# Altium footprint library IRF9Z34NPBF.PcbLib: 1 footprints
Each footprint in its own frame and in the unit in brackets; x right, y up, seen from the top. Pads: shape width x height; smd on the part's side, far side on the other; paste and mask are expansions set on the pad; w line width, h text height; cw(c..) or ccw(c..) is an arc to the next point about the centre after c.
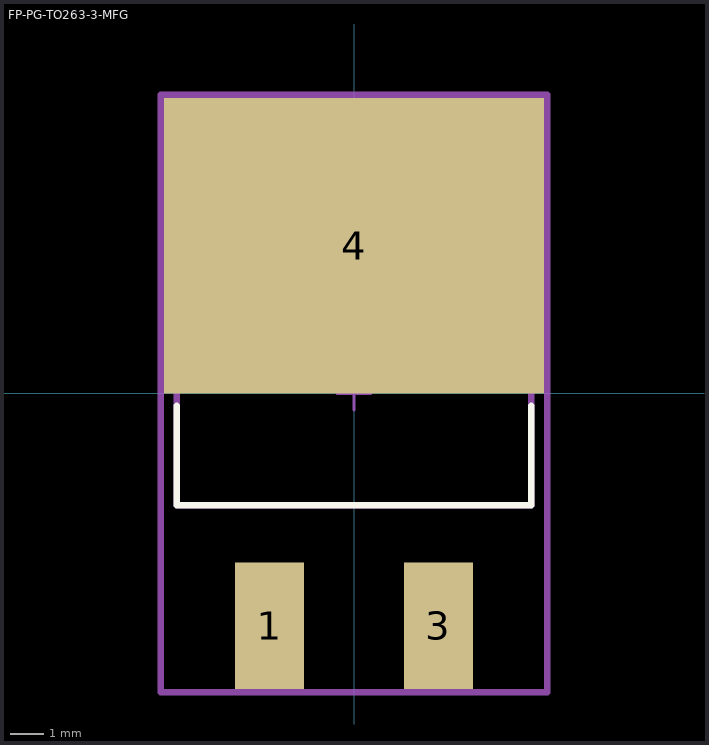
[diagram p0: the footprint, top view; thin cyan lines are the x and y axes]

## FP-PG-TO263-3-MFG [mm]
pads (3):
  rect 2.08x3.81 smd paste+0 mask+0: 1(-2.54,-6.985) 3(2.54,-6.985)
  rect 11.43x8.89 smd paste+0 mask+0: 4(0,4.445)
Top Overlay:
  lines w0.2: -5.335,-0.375 -5.335,-3.36 5.335,-3.36 5.335,-0.375
Top Assembly:
  lines w0.2: -5.815,-8.99 -5.815,8.99 5.815,8.99 5.815,-8.99 -5.815,-8.99
  text ".Designator" at 0,-0.001 h1
Top 3D Body:
  lines w0.2: -5.335,-3.36 -5.335,6.29 5.335,6.29 5.335,-3.36 -5.335,-3.36
Top Courtyard:
  lines w0.2: -5.815,-8.99 -5.815,8.99 5.815,8.99 5.815,-8.99 -5.815,-8.99
Top Component Center:
  lines w0.1: -0.5,0 0.5,0 ; 0,-0.5 0,0.5
3D body "Trans_Infineon_IRF2805STRLPBF_eec.STEP": height 0.25, standoff 0, extent -5.815,-8.99 5.815,8.99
